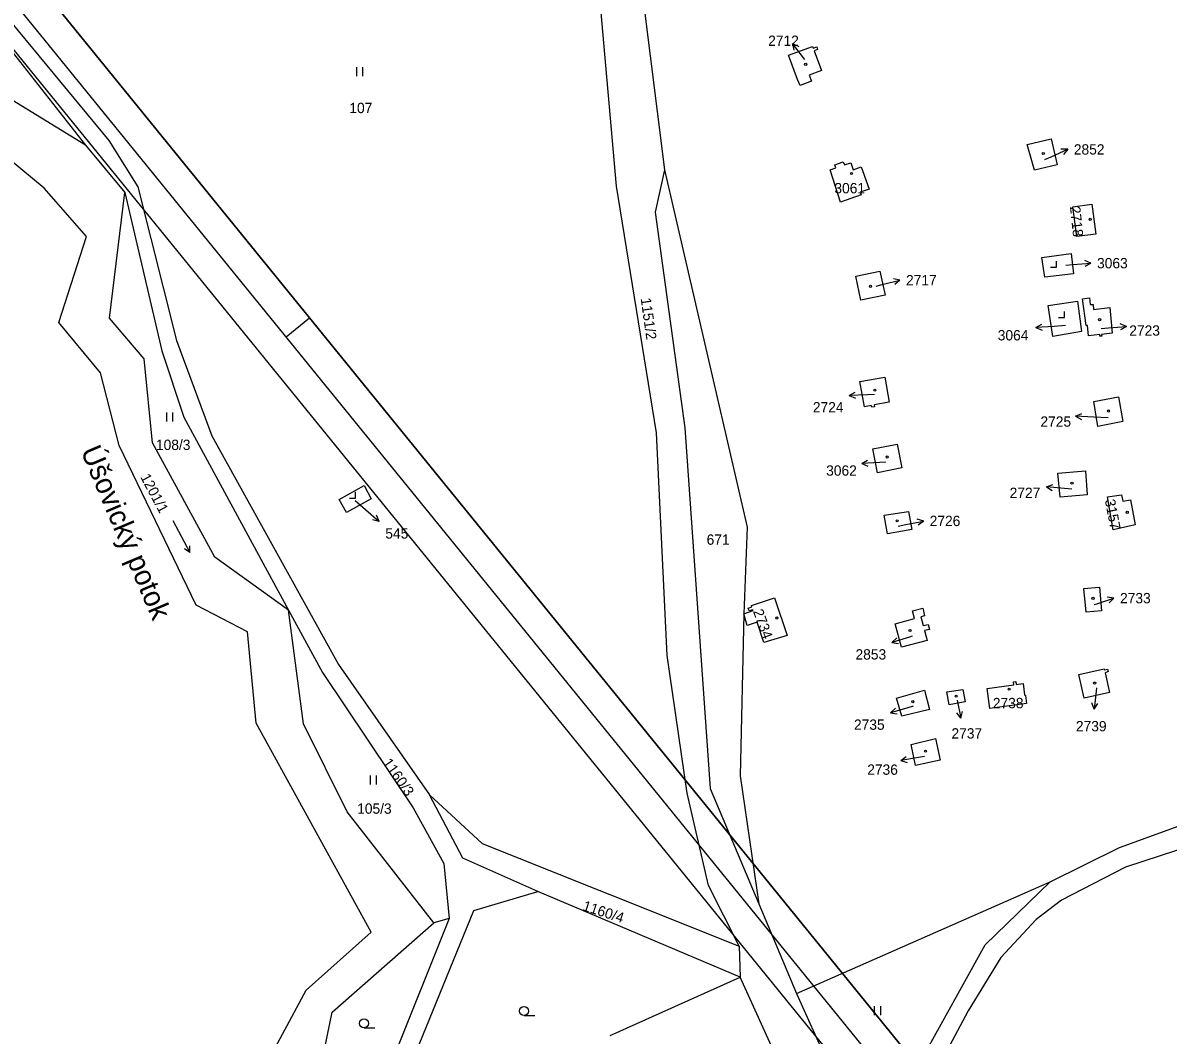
# Model space of a CAD drawing. Extents: x -866656 to -858817, y -1041816 to -1038653.
# Drawn here: x -866175.7 to -865986.9, y -1039314.8 to -1039148 of the extents above; entities that cross this region are included whole.
import ezdxf

# ---------------------------------------------------------------- set-up
doc = ezdxf.new("R2010")
doc.units = 0
for name, color, linetype in [('Hranice parcel', 7, 'Continuous'), ('Parcelní čísla', 7, 'Continuous'), ('Pop  PČ popisy', 7, 'Continuous'), ('tisk ramy', 7, 'Continuous'), ('Značky budov', 7, 'Continuous'), ('Značky kultur', 7, 'Continuous')]:
    doc.layers.add(name, color=color, linetype=linetype)

msp = doc.modelspace()

# ---------------------------------------------------------------- linework, layer by layer
at = {"layer": 'Hranice parcel'}
for p, q in [((-866194.34, -1039127.75), (-866161.48, -1039167.39)), ((-866196.01, -1039129.14), (-866165.35, -1039168.15)), ((-866074.58, -1039134.7), (-866069.9, -1039172.22)), ((-866077.83, -1039174.92), (-866080.58, -1039143.64)), ((-866049.48, -1039153.31), (-866045.48, -1039151.87)), ((-866047.99, -1039157.31), (-866049.48, -1039153.31)), ((-866045.48, -1039151.87), (-866045.4, -1039152.14)), ((-866045.4, -1039152.14), (-866044.8, -1039151.97)), ((-866044.69, -1039152.37), (-866045.24, -1039152.58)), ((-866045.24, -1039152.58), (-866044.02, -1039155.86)), ((-866044.8, -1039151.97), (-866044.69, -1039152.37)), ((-866165.35, -1039168.15), (-866187.74, -1039154.39)), ((-866047.54, -1039158.3), (-866047.99, -1039157.31)), ((-866044.02, -1039155.86), (-866046.06, -1039156.62)), ((-866046.06, -1039156.62), (-866045.69, -1039157.62)), ((-866045.69, -1039157.62), (-866047.54, -1039158.3)), ((-866172.13, -1039175.22), (-866185.96, -1039163.88)), ((-866165.35, -1039168.15), (-866158.87, -1039175.96)), ((-866161.48, -1039167.39), (-866156.69, -1039175.04)), ((-866010.1, -1039168.02), (-866006.16, -1039167.11)), ((-866008.9, -1039172.25), (-866010.1, -1039168.02)), ((-866006.16, -1039167.11), (-866005.17, -1039171.39)), ((-866069.9, -1039172.22), (-866071.44, -1039179.21)), ((-866069.9, -1039172.22), (-866056.29, -1039231.07)), ((-866042.58, -1039172.22), (-866041.63, -1039171.89)), ((-866040.9, -1039177.53), (-866042.58, -1039172.22)), ((-866041.81, -1039171.39), (-866040.45, -1039170.88)), ((-866041.63, -1039171.89), (-866041.81, -1039171.39)), ((-866040.45, -1039170.88), (-866040.25, -1039171.41)), ((-866040.25, -1039171.41), (-866039.2, -1039171.05)), ((-866039.2, -1039171.05), (-866038.81, -1039172.2)), ((-866038.81, -1039172.2), (-866037.46, -1039171.74)), ((-866037.46, -1039171.74), (-866036.18, -1039175.4)), ((-866005.17, -1039171.39), (-866008.9, -1039172.25)), ((-866165.18, -1039183.21), (-866172.13, -1039175.22)), ((-866161.4, -1039196.64), (-866158.87, -1039175.96)), ((-866158.87, -1039175.96), (-866152.76, -1039202.06)), ((-866156.69, -1039175.04), (-866150.33, -1039200.32)), ((-866071.22, -1039215.56), (-866077.83, -1039174.92)), ((-866036.18, -1039175.4), (-866037.65, -1039175.91)), ((-866037.65, -1039175.91), (-866037.49, -1039176.35)), ((-866037.49, -1039176.35), (-866040.9, -1039177.53)), ((-866002.61, -1039178.29), (-865999.46, -1039177.85)), ((-865999.46, -1039177.85), (-865998.81, -1039182.82)), ((-866071.44, -1039179.21), (-866066.55, -1039214.75)), ((-866001.92, -1039183.22), (-866002.61, -1039178.29)), ((-866169.74, -1039197.34), (-866165.18, -1039183.21)), ((-865998.81, -1039182.82), (-866001.92, -1039183.22)), ((-866007.69, -1039186.63), (-866002.86, -1039186.02)), ((-866007.22, -1039189.89), (-866007.69, -1039186.63)), ((-866002.86, -1039186.02), (-866002.45, -1039189.35)), ((-866038.33, -1039189.75), (-866034.39, -1039188.89)), ((-866034.39, -1039188.89), (-866033.54, -1039192.87)), ((-866002.45, -1039189.35), (-866007.22, -1039189.89)), ((-866037.54, -1039193.7), (-866038.33, -1039189.75)), ((-866033.54, -1039192.87), (-866037.54, -1039193.7)), ((-866006.66, -1039194.56), (-866001.81, -1039193.83)), ((-866005.9, -1039199.67), (-866006.66, -1039194.56)), ((-866001.81, -1039193.83), (-866001.14, -1039198.87)), ((-866001.01, -1039193.44), (-865999.84, -1039193.32)), ((-866000.37, -1039197.86), (-866001.01, -1039193.44)), ((-865999.84, -1039193.32), (-865999.7, -1039194.38)), ((-865999.7, -1039194.38), (-865999.25, -1039194.39)), ((-865999.25, -1039194.39), (-865999.19, -1039195.21)), ((-865999.19, -1039195.21), (-865996.51, -1039194.91)), ((-865996.51, -1039194.91), (-865996.12, -1039199.12)), ((-866155.66, -1039203.33), (-866161.4, -1039196.64)), ((-866162.87, -1039205.64), (-866169.74, -1039197.34)), ((-866001.14, -1039198.87), (-866005.9, -1039199.67)), ((-866000.17, -1039197.84), (-866000.37, -1039197.86)), ((-865999.98, -1039199.55), (-866000.17, -1039197.84)), ((-866150.33, -1039200.32), (-866144.54, -1039216.04)), ((-865998.15, -1039199.35), (-865999.98, -1039199.55)), ((-865998.12, -1039199.64), (-865998.15, -1039199.35)), ((-865997.81, -1039199.61), (-865998.12, -1039199.64)), ((-865996.12, -1039199.12), (-865997.84, -1039199.32)), ((-865997.84, -1039199.32), (-865997.81, -1039199.61)), ((-866152.76, -1039202.06), (-866149.13, -1039212.99)), ((-866154.28, -1039217.2), (-866155.66, -1039203.33)), ((-866159.8, -1039217.66), (-866162.87, -1039205.64)), ((-866037.71, -1039207.11), (-866033.57, -1039206.35)), ((-866033.57, -1039206.35), (-866032.85, -1039210.5)), ((-866036.94, -1039211.24), (-866037.71, -1039207.11)), ((-865999.14, -1039210.37), (-865995.07, -1039209.59)), ((-865995.07, -1039209.59), (-865994.34, -1039213.69)), ((-866035.81, -1039211.03), (-866036.94, -1039211.24)), ((-866035.7, -1039211.34), (-866035.81, -1039211.03)), ((-866035.27, -1039211.25), (-866035.7, -1039211.34)), ((-866032.85, -1039210.5), (-866035.32, -1039210.94)), ((-866035.32, -1039210.94), (-866035.27, -1039211.25)), ((-865998.45, -1039214.51), (-865999.14, -1039210.37)), ((-866149.13, -1039212.99), (-866131.86, -1039244.74)), ((-865994.34, -1039213.69), (-865998.45, -1039214.51)), ((-866069.46, -1039252.26), (-866071.22, -1039215.56)), ((-866066.55, -1039214.75), (-866062.38, -1039274.14)), ((-866147.09, -1039243.93), (-866159.8, -1039217.66)), ((-866144.03, -1039236.01), (-866154.28, -1039217.2)), ((-866144.54, -1039216.04), (-866123.62, -1039253.74)), ((-866035.53, -1039218.19), (-866031.55, -1039217.41)), ((-866031.55, -1039217.41), (-866030.76, -1039221.34)), ((-866034.79, -1039222.12), (-866035.53, -1039218.19)), ((-866030.76, -1039221.34), (-866034.79, -1039222.12)), ((-866005.05, -1039222.22), (-866000.49, -1039221.83)), ((-866004.69, -1039226.14), (-866005.05, -1039222.22)), ((-866000.49, -1039221.83), (-866000.23, -1039225.76)), ((-866123.52, -1039226.55), (-866119.43, -1039224.24)), ((-866119.43, -1039224.24), (-866118.26, -1039226.42)), ((-866122.3, -1039228.7), (-866123.52, -1039226.55)), ((-866118.26, -1039226.42), (-866122.3, -1039228.7)), ((-866000.23, -1039225.76), (-866004.69, -1039226.14)), ((-865996.87, -1039226.11), (-865994.58, -1039225.75)), ((-865995.93, -1039231.55), (-865996.87, -1039226.11)), ((-865994.58, -1039225.75), (-865994.35, -1039226.81)), ((-865994.35, -1039226.81), (-865993.05, -1039226.61)), ((-865993.05, -1039226.61), (-865992.3, -1039230.7)), ((-866033.7, -1039229.13), (-866029.65, -1039228.5)), ((-866033.15, -1039232.21), (-866033.7, -1039229.13)), ((-866029.65, -1039228.5), (-866029.13, -1039231.46)), ((-865992.3, -1039230.7), (-865995.93, -1039231.55)), ((-866056.29, -1039231.07), (-866056.84, -1039245.35)), ((-866029.13, -1039231.46), (-866033.15, -1039232.21)), ((-866131.86, -1039244.74), (-866144.03, -1039236.01)), ((-866000.75, -1039241.18), (-865998.16, -1039240.95)), ((-866000.37, -1039245.07), (-866000.75, -1039241.18)), ((-865998.16, -1039240.95), (-865997.83, -1039244.85)), ((-866138.65, -1039248.34), (-866147.09, -1039243.93)), ((-866056.12, -1039244.42), (-866055.5, -1039244.21)), ((-866055.56, -1039244.02), (-866051.78, -1039242.76)), ((-866055.5, -1039244.21), (-866055.56, -1039244.02)), ((-866051.78, -1039242.76), (-866049.67, -1039248.92)), ((-866129.39, -1039263.51), (-866131.86, -1039244.74)), ((-866131.86, -1039244.74), (-866126.27, -1039255.06)), ((-866056.84, -1039245.35), (-866057.4, -1039272.04)), ((-866056.84, -1039245.35), (-866055.29, -1039244.83)), ((-866056.25, -1039247.31), (-866056.84, -1039245.35)), ((-866055.96, -1039244.89), (-866056.12, -1039244.42)), ((-866055.34, -1039244.69), (-866055.96, -1039244.89)), ((-866055.29, -1039244.83), (-866055.34, -1039244.69)), ((-866031.87, -1039247.03), (-866028.67, -1039246.16)), ((-866029.04, -1039244.86), (-866027.33, -1039244.46)), ((-866028.67, -1039246.16), (-866029.04, -1039244.86)), ((-866027.03, -1039245.7), (-866027.63, -1039245.88)), ((-866027.63, -1039245.88), (-866027.26, -1039247.27)), ((-866027.33, -1039244.46), (-866027.03, -1039245.7)), ((-865997.83, -1039244.85), (-866000.37, -1039245.07)), ((-866054.64, -1039246.77), (-866056.25, -1039247.31)), ((-866053.52, -1039250.11), (-866054.64, -1039246.77)), ((-866030.82, -1039250.87), (-866031.87, -1039247.03)), ((-866027.26, -1039247.27), (-866026.41, -1039247.13)), ((-866026.2, -1039247.96), (-866027.03, -1039248.09)), ((-866026.41, -1039247.13), (-866026.2, -1039247.96)), ((-866137.23, -1039263.39), (-866138.65, -1039248.34)), ((-866049.67, -1039248.92), (-866053.52, -1039250.11)), ((-866026.59, -1039249.75), (-866030.82, -1039250.87)), ((-866027.03, -1039248.09), (-866026.59, -1039249.75)), ((-866066.18, -1039274.94), (-866069.46, -1039252.26)), ((-866126.27, -1039255.06), (-866111.31, -1039277.34)), ((-866123.62, -1039253.74), (-866108.65, -1039275.2)), ((-866001.58, -1039255.36), (-865997.41, -1039254.44)), ((-866000.69, -1039259.24), (-866001.58, -1039255.36)), ((-865997.41, -1039254.44), (-865997.37, -1039254.62)), ((-865997.37, -1039254.62), (-865996.86, -1039254.5)), ((-865996.78, -1039254.89), (-865997.26, -1039255.1)), ((-865997.26, -1039255.1), (-865996.55, -1039258.34)), ((-865996.86, -1039254.5), (-865996.78, -1039254.89)), ((-866016.7, -1039257.68), (-866012.32, -1039257.08)), ((-866012.39, -1039256.58), (-866011.96, -1039256.53)), ((-866012.32, -1039257.08), (-866012.39, -1039256.58)), ((-866011.96, -1039256.53), (-866011.9, -1039257.02)), ((-866011.9, -1039257.02), (-866010.78, -1039256.87)), ((-866010.78, -1039256.87), (-866010.53, -1039258.72)), ((-866031.65, -1039259.29), (-866027.03, -1039257.95)), ((-866030.77, -1039262.23), (-866031.65, -1039259.29)), ((-866027.03, -1039257.95), (-866026.2, -1039261.12)), ((-866023.35, -1039258.21), (-866020.69, -1039257.84)), ((-866022.95, -1039260.34), (-866023.35, -1039258.21)), ((-866020.69, -1039257.84), (-866020.31, -1039259.88)), ((-866016.25, -1039260.96), (-866016.7, -1039257.68)), ((-866010.53, -1039258.72), (-866010.4, -1039258.82)), ((-866010.4, -1039258.82), (-866010.22, -1039260.13)), ((-865996.55, -1039258.34), (-866000.69, -1039259.24)), ((-866026.2, -1039261.12), (-866030.77, -1039262.23)), ((-866020.31, -1039259.88), (-866022.95, -1039260.34)), ((-866010.22, -1039260.13), (-866016.25, -1039260.96)), ((-866118.23, -1039297.83), (-866137.23, -1039263.39)), ((-866122.23, -1039277.99), (-866129.39, -1039263.51)), ((-866029.25, -1039266.9), (-866025.22, -1039265.93)), ((-866028.54, -1039270.38), (-866029.25, -1039266.9)), ((-866025.22, -1039265.93), (-866024.46, -1039269.49)), ((-866024.46, -1039269.49), (-866028.54, -1039270.38)), ((-866057.4, -1039272.04), (-866054.37, -1039293.17)), ((-866062.38, -1039274.14), (-866054.37, -1039293.17)), ((-865994.91, -1039283.88), (-865965.62, -1039273.21)), ((-866103.15, -1039285.63), (-866108.65, -1039275.2)), ((-866108.65, -1039275.2), (-866099.98, -1039283.2)), ((-866062.66, -1039290.11), (-866066.18, -1039274.94)), ((-866107.92, -1039296.29), (-866122.23, -1039277.99)), ((-866111.31, -1039277.34), (-866106.29, -1039286.49)), ((-865964.37, -1039277.46), (-865993.89, -1039287.14)), ((-866099.98, -1039283.2), (-866057.56, -1039300.14)), ((-866006.34, -1039289.55), (-865994.91, -1039283.88)), ((-866090.8, -1039291.12), (-866103.15, -1039285.63)), ((-866106.29, -1039286.49), (-866105.38, -1039295.56)), ((-865993.89, -1039287.14), (-866004.43, -1039292.54)), ((-866048.15, -1039307.93), (-866006.34, -1039289.55)), ((-866017.02, -1039299.91), (-866006.34, -1039289.55)), ((-866101.35, -1039294.25), (-866090.8, -1039291.12)), ((-866057.44, -1039305.25), (-866090.8, -1039291.12)), ((-866057.56, -1039300.14), (-866062.66, -1039290.11)), ((-866054.37, -1039293.17), (-866048.15, -1039307.93)), ((-866004.43, -1039292.54), (-866008.64, -1039295.71)), ((-866118.2, -1039335.68), (-866101.35, -1039294.25)), ((-866124.67, -1039311.03), (-866107.92, -1039296.29)), ((-866105.38, -1039295.56), (-866121.18, -1039334.91)), ((-866105.38, -1039295.56), (-866107.92, -1039296.29)), ((-866008.64, -1039295.71), (-866014.43, -1039302.01)), ((-866128.95, -1039307.39), (-866118.23, -1039297.83)), ((-866057.56, -1039300.14), (-866057.44, -1039305.25)), ((-866028.64, -1039320.79), (-866017.02, -1039299.91)), ((-866014.43, -1039302.01), (-866019.82, -1039310.81)), ((-866078.86, -1039314.87), (-866057.44, -1039305.25)), ((-866044.44, -1039333.64), (-866057.44, -1039305.25)), ((-866136.58, -1039321.45), (-866128.95, -1039307.39)), ((-866048.15, -1039307.93), (-866032.91, -1039341.46)), ((-866129.75, -1039335.49), (-866124.67, -1039311.03)), ((-866019.82, -1039310.81), (-866026.21, -1039322.66))]:
    msp.add_line(p, q, dxfattribs=at)
at = {"layer": 'Pop  PČ popisy'}
for p, q in [((-866046.97, -1039153.78), (-866048.78, -1039151.38)), ((-866048.78, -1039151.38), (-866047.77, -1039151.88)), ((-866048.78, -1039151.38), (-866048.57, -1039152.48)), ((-866046.78, -1039154.04), (-866046.97, -1039153.78)), ((-866007.22, -1039170.51), (-866006.17, -1039170.05)), ((-866006.17, -1039170.05), (-866003.43, -1039168.83)), ((-866003.43, -1039168.83), (-866004.55, -1039168.78)), ((-866003.43, -1039168.83), (-866004.14, -1039169.69)), ((-866002.58, -1039187.83), (-865999.59, -1039187.57)), ((-865999.59, -1039187.57), (-866000.63, -1039187.16)), ((-865999.59, -1039187.57), (-866000.54, -1039188.16)), ((-866003.76, -1039187.93), (-866002.58, -1039187.83)), ((-866034.99, -1039191.37), (-866033.99, -1039191.12)), ((-866033.99, -1039191.12), (-866031.08, -1039190.39)), ((-866031.08, -1039190.39), (-866032.17, -1039190.15)), ((-866031.08, -1039190.39), (-866031.93, -1039191.12)), ((-866008.66, -1039198.21), (-866007.7, -1039197.64)), ((-866005.67, -1039198), (-866008.66, -1039198.21)), ((-866008.66, -1039198.21), (-866007.63, -1039198.64)), ((-866003.77, -1039197.87), (-866005.67, -1039198)), ((-865997.93, -1039198.33), (-865996.73, -1039198.24)), ((-865996.73, -1039198.24), (-865993.74, -1039198.03)), ((-865993.74, -1039198.03), (-865994.77, -1039197.6)), ((-865993.74, -1039198.03), (-865994.7, -1039198.6)), ((-866039.43, -1039209.38), (-866038.45, -1039208.84)), ((-866036.43, -1039209.27), (-866039.43, -1039209.38)), ((-866039.43, -1039209.38), (-866038.41, -1039209.84)), ((-866035.28, -1039209.24), (-866036.43, -1039209.27)), ((-866002.14, -1039212.81), (-866001.11, -1039212.36)), ((-865999.14, -1039212.97), (-866002.14, -1039212.81)), ((-866002.14, -1039212.81), (-866001.16, -1039213.36)), ((-865996.74, -1039213.1), (-865999.14, -1039212.97)), ((-866037.39, -1039220.59), (-866036.41, -1039220.04)), ((-866034.39, -1039220.43), (-866037.39, -1039220.59)), ((-866037.39, -1039220.59), (-866036.36, -1039221.04)), ((-866033.43, -1039220.38), (-866034.39, -1039220.43)), ((-866006.92, -1039224.47), (-866005.88, -1039224.06)), ((-866003.93, -1039224.73), (-866006.92, -1039224.47)), ((-866006.92, -1039224.47), (-866005.97, -1039225.06)), ((-866002.75, -1039224.83), (-866003.93, -1039224.73)), ((-866120.89, -1039226.72), (-866119.19, -1039228.18)), ((-866119.19, -1039228.18), (-866116.93, -1039230.15)), ((-866116.93, -1039230.15), (-866117.35, -1039229.11)), ((-866116.93, -1039230.15), (-866118.01, -1039229.87)), ((-866031.39, -1039230.91), (-866030.12, -1039230.65)), ((-866030.12, -1039230.65), (-866027.17, -1039230.08)), ((-866027.17, -1039230.08), (-866028.25, -1039229.78)), ((-866027.17, -1039230.08), (-866028.06, -1039230.76)), ((-865999.08, -1039243.85), (-865998.65, -1039243.71)), ((-865998.65, -1039243.71), (-865995.8, -1039242.78)), ((-865995.8, -1039242.78), (-865996.9, -1039242.62)), ((-865995.8, -1039242.78), (-865996.59, -1039243.57)), ((-866029.53, -1039249.19), (-866032.4, -1039250.07)), ((-866032.4, -1039250.07), (-866031.59, -1039249.3)), ((-866029.08, -1039249.05), (-866029.53, -1039249.19)), ((-866032.4, -1039250.07), (-866031.3, -1039250.25)), ((-865998.75, -1039258.11), (-865999.06, -1039261.09)), ((-865998.7, -1039257.59), (-865998.75, -1039258.11)), ((-866029.76, -1039260.84), (-866032.65, -1039261.67)), ((-866032.65, -1039261.67), (-866031.82, -1039260.91)), ((-866028.93, -1039260.6), (-866029.76, -1039260.84)), ((-866021.66, -1039259.61), (-866021.66, -1039259.62)), ((-866021.66, -1039259.62), (-866021.04, -1039262.56)), ((-865999.06, -1039261.09), (-865999.46, -1039260.05)), ((-865999.06, -1039261.09), (-865998.46, -1039260.15)), ((-866032.65, -1039261.67), (-866031.54, -1039261.87)), ((-866021.04, -1039262.56), (-866021.73, -1039261.68)), ((-866021.04, -1039262.56), (-866020.75, -1039261.47)), ((-866030.96, -1039269.52), (-866030.05, -1039268.87)), ((-866028, -1039269.05), (-866030.96, -1039269.52)), ((-866030.96, -1039269.52), (-866029.9, -1039269.86)), ((-866027.04, -1039268.89), (-866028, -1039269.05))]:
    msp.add_line(p, q, dxfattribs=at)
at = {"layer": 'tisk ramy'}
msp.add_line((-866128.39, -1039196.63), (-866132.27, -1039199.78), dxfattribs=at)
for points in [[(-866268.65, -1039040.03), (-865473.6, -1040017.5), (-865243.2, -1039830.1), (-866038.25, -1038852.63)], [(-866038.97, -1038859.66), (-865250.23, -1039829.38), (-865472.87, -1040010.47), (-866261.62, -1039040.75)], [(-866254.59, -1039041.47), (-865601.5, -1039844.41), (-865386.61, -1039669.62), (-866039.7, -1038866.69)], [(-866039.7, -1038866.69), (-865386.61, -1039669.62), (-865601.5, -1039844.41), (-866254.59, -1039041.47)]]:
    msp.add_lwpolyline(points, close=True, dxfattribs=at)
at = {"layer": 'Značky budov'}
for centre in [(-866046.62, -1039154.82), (-866007.45, -1039169.53), (-866039.08, -1039172.81), (-865999.72, -1039180.36), (-866035.94, -1039191.41), (-865998.16, -1039196.89), (-866035.23, -1039208.52), (-865996.71, -1039211.95), (-866033.19, -1039219.53), (-866002.72, -1039223.85), (-865993.61, -1039228.65), (-866031.53, -1039230.06), (-865999.26, -1039242.82), (-866051.38, -1039246.06), (-866029.43, -1039248.11), (-865998.99, -1039256.78), (-866021.82, -1039258.95), (-866013.08, -1039257.79), (-866028.96, -1039259.85), (-866026.88, -1039267.99)]:
    msp.add_circle(centre, 0.175, dxfattribs=at)
at = {"layer": 'Značky kultur'}
for p, q in [((-866120.63, -1039156.77), (-866120.63, -1039155.27)), ((-866119.63, -1039156.77), (-866119.63, -1039155.27)), ((-866005.29, -1039188.27), (-866005.29, -1039187.27)), ((-866006.29, -1039188.27), (-866005.29, -1039188.27)), ((-866004.95, -1039196.56), (-866003.95, -1039196.56)), ((-866003.95, -1039196.56), (-866003.95, -1039195.56)), ((-866151.94, -1039213.69), (-866151.94, -1039212.19)), ((-866150.94, -1039213.69), (-866150.94, -1039212.19)), ((-866120.83, -1039226.29), (-866120.83, -1039225.29)), ((-866121.83, -1039226.29), (-866120.83, -1039226.29)), ((-866150.96, -1039229.97), (-866148.14, -1039235.27)), ((-866148.14, -1039235.27), (-866149.04, -1039234.64)), ((-866148.14, -1039235.27), (-866148.16, -1039234.17)), ((-866118.38, -1039273.51), (-866118.38, -1039272.01)), ((-866117.38, -1039273.51), (-866117.38, -1039272.01)), ((-866035.26, -1039311.5), (-866035.26, -1039310)), ((-866034.26, -1039311.5), (-866034.26, -1039310)), ((-866093.04, -1039311.58), (-866091.29, -1039311.58)), ((-866119.42, -1039313.6), (-866117.67, -1039313.6))]:
    msp.add_line(p, q, dxfattribs=at)
for centre in [(-866093.04, -1039310.83), (-866119.42, -1039312.85)]:
    msp.add_circle(centre, 0.75, dxfattribs=at)

# ---------------------------------------------------------------- texts
at = {"layer": 'Parcelní čísla'}
for s, p in [('2712', (-866052.81, -1039151.79)), ('107', (-866121.85, -1039162.87)), ('2852', (-866002.42, -1039169.7)), ('3061', (-866041.89, -1039176.08)), ('3063', (-865998.59, -1039188.44)), ('2717', (-866030.08, -1039191.24)), ('3064', (-866014.96, -1039200.32)), ('2723', (-865993.28, -1039199.54)), ('2724', (-866045.44, -1039212.18)), ('2725', (-866007.92, -1039214.54)), ('108/3', (-866153.73, -1039218.37)), ('3062', (-866043.25, -1039222.61)), ('2727', (-866013, -1039226.28)), ('2726', (-866026.18, -1039230.91)), ('545', (-866115.92, -1039232.97)), ('671', (-866062.95, -1039233.99)), ('2733', (-865994.8, -1039243.63)), ('2853', (-866038.41, -1039252.9)), ('2738', (-866015.77, -1039260.92)), ('2735', (-866038.66, -1039264.48)), ('2739', (-866002.08, -1039264.73)), ('2737', (-866022.59, -1039265.92)), ('2736', (-866036.48, -1039271.89)), ('105/3', (-866120.56, -1039278.31))]:
    msp.add_text(s, height=1.7, dxfattribs=at).set_placement(p)
for s, rotation, p in [('2718', 276, (-866003.06, -1039178.3)), ('1151/2', 278, (-866073.83, -1039193.42)), ('1201/1', 298, (-866156.35, -1039222.82)), ('3157', 281, (-865997.32, -1039226.64)), ('2734', 290, (-866055.33, -1039244.94)), ('1160/3', 305, (-866116.43, -1039269.9)), ('1160/4', 342, (-866083.52, -1039294.19))]:
    msp.add_text(s, height=1.7, rotation=rotation, dxfattribs=at).set_placement(p)
at = {"layer": 'Pop  PČ popisy'}
msp.add_text('Úšovický potok', height=3.4, rotation=293, dxfattribs=at).set_placement((-866166.18, -1039218.52))

doc.saveas('drawing.dxf')
